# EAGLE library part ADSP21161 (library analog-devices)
DSP Microcomputer
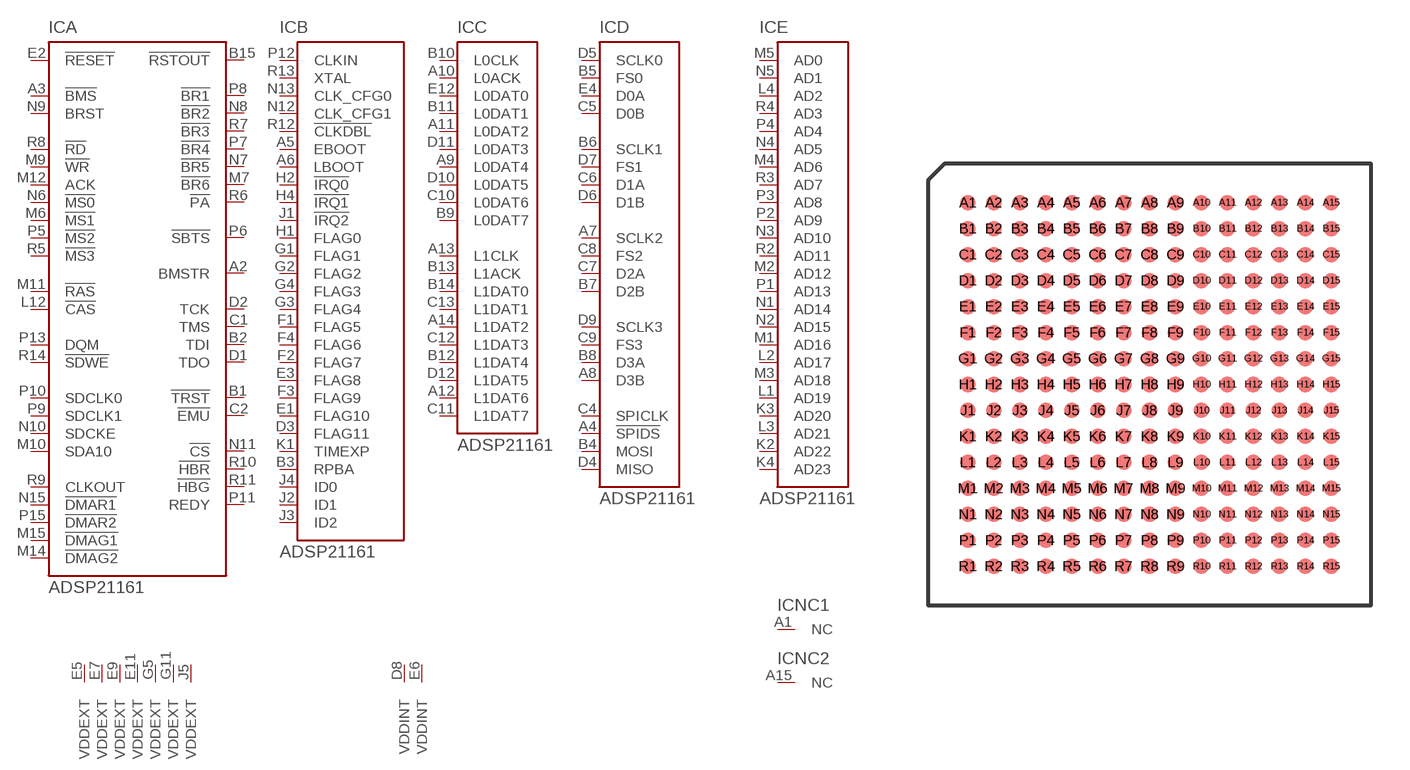
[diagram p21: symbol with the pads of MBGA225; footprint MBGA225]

Designator prefix IC; gates E=ADSP-21161-ADR NC1=NC NC2=NC B=ADSP-21161-CTRL1 A=ADSP-21161-CTRL2 C=ADSP-21161-PAR D=ADSP-21161-SER VE1=VDDEXT VE2=VDDEXT VE3=VDDEXT VE4=VDDEXT VE5=VDDEXT VE6=VDDEXT VE7=VDDEXT VI1=VDDINT VI2=VDDINT VI3=VDDINT VI4=VDDINT VI5=VDDINT VI6=VDDINT VI7=VDDINT G1=GND G2=GND G3=GND G4=GND G5=GND G6=GND G7=GND G8=GND G9=GND G10=GND G11=GND G12=GND G13=GND G14=GND G15=GND G16=GND G17=GND F=ADSP-21161-DATA VE8=VDDEXT VE9=VDDEXT VE10=VDDEXT VE11=VDDEXT VE12=VDDEXT VI8=VDDINT VI9=VDDINT VI10=VDDINT VI11=VDDINT VI12=VDDINT VI13=VDDINT G18=GND G19=GND G20=GND G21=GND G22=GND G23=GND G24=GND G25=GND G26=GND VE13=VDDEXT VI14=VDDINT AV=AVDD AG=AGND NC3=NC NC4=NC

## ADSP21161 (MF: ALTERA CORPORATION; MPN: ADSP-21161NCCA-100; OC_FARNELL: 1465539; OC_NEWARK: 02H1229)  [MBGA225]
A1  NC1:NC  nc
A2  A:BMSTR  out
A3  A:!BMS
A4  D:!SPIDS  in
A5  B:EBOOT  in
A6  B:LBOOT  in
A7  D:SCLK2
A8  D:D3B
A9  C:L0DAT4
A10  C:L0ACK
A11  C:L0DAT2
A12  C:L1DAT6
A13  C:L1CLK
A14  C:L1DAT2
A15  NC2:NC  nc
B1  A:!TRST  in
B2  A:TDI  in
B3  B:RPBA  in
B4  D:MOSI
B5  D:FS0
B6  D:SCLK1
B7  D:D2B
B8  D:D3A
B9  C:L0DAT7
B10  C:L0CLK
B11  C:L0DAT1
B12  C:L1DAT4
B13  C:L1ACK
B14  C:L1DAT0
B15  A:!RSTOUT  out
C1  A:TMS  in
C2  A:!EMU  out
C3  G1:GND  pwr
C4  D:SPICLK
C5  D:D0B
C6  D:D1A
C7  D:D2A
C8  D:FS2
C9  D:FS3
C10  C:L0DAT6
C11  C:L1DAT7
C12  C:L1DAT3
C13  C:L1DAT1
C14  F:D45  hiz
C15  F:D47  hiz
D1  A:TDO  out
D2  A:TCK  in
D3  B:FLAG11
D4  D:MISO
D5  D:SCLK0
D6  D:D1B
D7  D:FS1
D8  VI1:VDDINT  pwr
D9  D:SCLK3
D10  C:L0DAT5
D11  C:L0DAT3
D12  C:L1DAT5
D13  F:D42  hiz
D14  F:D46  hiz
D15  F:D44  hiz
E1  B:FLAG10
E2  A:!RESET  in
E3  B:FLAG8
E4  D:D0A
E5  VE1:VDDEXT  pwr
E6  VI2:VDDINT  pwr
E7  VE2:VDDEXT  pwr
E8  VI3:VDDINT  pwr
E9  VE3:VDDEXT  pwr
E10  VI4:VDDINT  pwr
E11  VE4:VDDEXT  pwr
E12  C:L0DAT0
E13  F:D39  hiz
E14  F:D43  hiz
E15  F:D41  hiz
F1  B:FLAG5
F2  B:FLAG7
F3  B:FLAG9
F4  B:FLAG6
F5  VI5:VDDINT  pwr
F6  G10:GND  pwr
F7  G11:GND  pwr
F8  G12:GND  pwr
F9  G13:GND  pwr
F10  G14:GND  pwr
F11  VI6:VDDINT  pwr
F12  F:D37  hiz
F13  F:D40  hiz
F14  F:D38  hiz
F15  F:D36  hiz
G1  B:FLAG1
G2  B:FLAG2
G3  B:FLAG4
G4  B:FLAG3
G5  VE5:VDDEXT  pwr
G6  G2:GND  pwr
G7  G3:GND  pwr
G8  G4:GND  pwr
G9  G5:GND  pwr
G10  G6:GND  pwr
G11  VE6:VDDEXT  pwr
G12  F:D34  hiz
G13  F:D35  hiz
G14  F:D33  hiz
G15  F:D32  hiz
H1  B:FLAG0
H2  B:!IRQ0  in
H3  VI7:VDDINT  pwr
H4  B:!IRQ1  in
H5  VI8:VDDINT  pwr
H6  G7:GND  pwr
H7  G8:GND  pwr
H8  G9:GND  pwr
H9  G15:GND  pwr
H10  G16:GND  pwr
H11  VI9:VDDINT  pwr
H12  F:D29  hiz
H13  F:D28  hiz
H14  F:D30  hiz
H15  F:D31  hiz
J1  B:!IRQ2  in
J2  B:ID1  in
J3  B:ID2  in
J4  B:ID0  in
J5  VE7:VDDEXT  pwr
J6  G17:GND  pwr
J7  G18:GND  pwr
J8  G19:GND  pwr
J9  G20:GND  pwr
J10  G21:GND  pwr
J11  VE8:VDDEXT  pwr
J12  F:D26  hiz
J13  F:D24  hiz
J14  F:D25  hiz
J15  F:D27  hiz
K1  B:TIMEXP  out
K2  E:AD22  hiz
K3  E:AD20  hiz
K4  E:AD23  hiz
K5  VI10:VDDINT  pwr
K6  G22:GND  pwr
K7  G23:GND  pwr
K8  G24:GND  pwr
K9  G25:GND  pwr
K10  G26:GND  pwr
K11  VI11:VDDINT  pwr
K12  F:D22  hiz
K13  F:D19  hiz
K14  F:D21  hiz
K15  F:D23  hiz
L1  E:AD19  hiz
L2  E:AD17  hiz
L3  E:AD21  hiz
L4  E:AD2  hiz
L5  VE9:VDDEXT  pwr
L6  VI12:VDDINT  pwr
L7  VE10:VDDEXT  pwr
L8  VI13:VDDINT  pwr
L9  VE11:VDDEXT  pwr
L10  VI14:VDDINT  pwr
L11  VE12:VDDEXT  pwr
L12  A:!CAS
L13  F:D20  hiz
L14  F:D16  hiz
L15  F:D18  hiz
M1  E:AD16  hiz
M2  E:AD12  hiz
M3  E:AD18  hiz
M4  E:AD6  hiz
M5  E:AD0  hiz
M6  A:!MS1  hiz
M7  A:!BR6
M8  VE13:VDDEXT  pwr
M9  A:!WR  hiz
M10  A:SDA10  out
M11  A:!RAS
M12  A:ACK
M13  F:D17  hiz
M14  A:!DMAG2  out
M15  A:!DMAG1  out
N1  E:AD14  hiz
N2  E:AD15  hiz
N3  E:AD10  hiz
N4  E:AD5  hiz
N5  E:AD1  hiz
N6  A:!MS0  hiz
N7  A:!BR5
N8  A:!BR2
N9  A:BRST  hiz
N10  A:SDCKE
N11  A:!CS  in
N12  B:CLK_CFG1  in
N13  B:CLK_CFG0  in
N14  AV:AVDD  pwr
N15  A:!DMAR1  in
P1  E:AD13  hiz
P2  E:AD9  hiz
P3  E:AD8  hiz
P4  E:AD4  hiz
P5  A:!MS2  hiz
P6  A:!SBTS  in
P7  A:!BR4
P8  A:!BR1
P9  A:SDCLK1  out
P10  A:SDCLK0
P11  A:REDY  out
P12  B:CLKIN  in
P13  A:DQM  out
P14  AG:AGND  pwr
P15  A:!DMAR2  in
R1  NC3:NC  nc
R2  E:AD11  hiz
R3  E:AD7  hiz
R4  E:AD3  hiz
R5  A:!MS3  hiz
R6  A:!PA
R7  A:!BR3
R8  A:!RD  hiz
R9  A:CLKOUT  out
R10  A:!HBR  in
R11  A:!HBG
R12  B:!CLKDBL  in
R13  B:XTAL  out
R14  A:!SDWE
R15  NC4:NC  nc

## Footprint MBGA225 (pad centres in mm)
Micro Ball Grid Aray 225
smd 0.6 x 0.6: A1 -7,7; A2 -6,7; A3 -5,7; A4 -4,7; A5 -3,7; A6 -2,7; A7 -1,7; A8 0,7; A9 1,7; A10 2,7; A11 3,7; A12 4,7; A13 5,7; A14 6,7; A15 7,7; B1 -7,6; B2 -6,6; B3 -5,6; B4 -4,6; B5 -3,6; B6 -2,6; B7 -1,6; B8 0,6; B9 1,6; B10 2,6; B11 3,6; B12 4,6; B13 5,6; B14 6,6; B15 7,6; C1 -7,5; C2 -6,5; C3 -5,5; C4 -4,5; C5 -3,5; C6 -2,5; C7 -1,5; C8 0,5; C9 1,5; C10 2,5; C11 3,5; C12 4,5; C13 5,5; C14 6,5; C15 7,5; D1 -7,4; D2 -6,4; D3 -5,4; D4 -4,4; D5 -3,4; D6 -2,4; D7 -1,4; D8 0,4; D9 1,4; D10 2,4; D11 3,4; D12 4,4; D13 5,4; D14 6,4; D15 7,4; E1 -7,3; E2 -6,3; E3 -5,3; E4 -4,3; E5 -3,3; E6 -2,3; E7 -1,3; E8 0,3; E9 1,3; E10 2,3; E11 3,3; E12 4,3; E13 5,3; E14 6,3; E15 7,3; F1 -7,2; F2 -6,2; F3 -5,2; F4 -4,2; F5 -3,2; F6 -2,2; F7 -1,2; F8 0,2; F9 1,2; F10 2,2; F11 3,2; F12 4,2; F13 5,2; F14 6,2; F15 7,2; G1 -7,1; G2 -6,1; G3 -5,1; G4 -4,1; G5 -3,1; G6 -2,1; G7 -1,1; G8 0,1; G9 1,1; G10 2,1; G11 3,1; G12 4,1; G13 5,1; G14 6,1; G15 7,1; H1 -7,0; H2 -6,0; H3 -5,0; H4 -4,0; H5 -3,0; H6 -2,0; H7 -1,0; H8 0,0; H9 1,0; H10 2,0; H11 3,0; H12 4,0; H13 5,0; H14 6,0; H15 7,0; J1 -7,-1; J2 -6,-1; J3 -5,-1; J4 -4,-1; J5 -3,-1; J6 -2,-1; J7 -1,-1; J8 0,-1; J9 1,-1; J10 2,-1; J11 3,-1; J12 4,-1; J13 5,-1; J14 6,-1; J15 7,-1; K1 -7,-2; K2 -6,-2; K3 -5,-2; K4 -4,-2; K5 -3,-2; K6 -2,-2; K7 -1,-2; K8 0,-2; K9 1,-2; K10 2,-2; K11 3,-2; K12 4,-2; K13 5,-2; K14 6,-2; K15 7,-2; L1 -7,-3; L2 -6,-3; L3 -5,-3; L4 -4,-3; L5 -3,-3; L6 -2,-3; L7 -1,-3; L8 0,-3; L9 1,-3; L10 2,-3; L11 3,-3; L12 4,-3; L13 5,-3; L14 6,-3; L15 7,-3; M1 -7,-4; M2 -6,-4; M3 -5,-4; M4 -4,-4; M5 -3,-4; M6 -2,-4; M7 -1,-4; M8 0,-4; M9 1,-4; M10 2,-4; M11 3,-4; M12 4,-4; M13 5,-4; M14 6,-4; M15 7,-4; N1 -7,-5; N2 -6,-5; N3 -5,-5; N4 -4,-5; N5 -3,-5; N6 -2,-5; N7 -1,-5; N8 0,-5; N9 1,-5; N10 2,-5; N11 3,-5; N12 4,-5; N13 5,-5; N14 6,-5; N15 7,-5; P1 -7,-6; P2 -6,-6; P3 -5,-6; P4 -4,-6; P5 -3,-6; P6 -2,-6; P7 -1,-6; P8 0,-6; P9 1,-6; P10 2,-6; P11 3,-6; P12 4,-6; P13 5,-6; P14 6,-6; P15 7,-6; R1 -7,-7; R2 -6,-7; R3 -5,-7; R4 -4,-7; R5 -3,-7; R6 -2,-7; R7 -1,-7; R8 0,-7; R9 1,-7; R10 2,-7; R11 3,-7; R12 4,-7; R13 5,-7; R14 6,-7; R15 7,-7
